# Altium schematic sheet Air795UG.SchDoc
size 431 x 279 mm
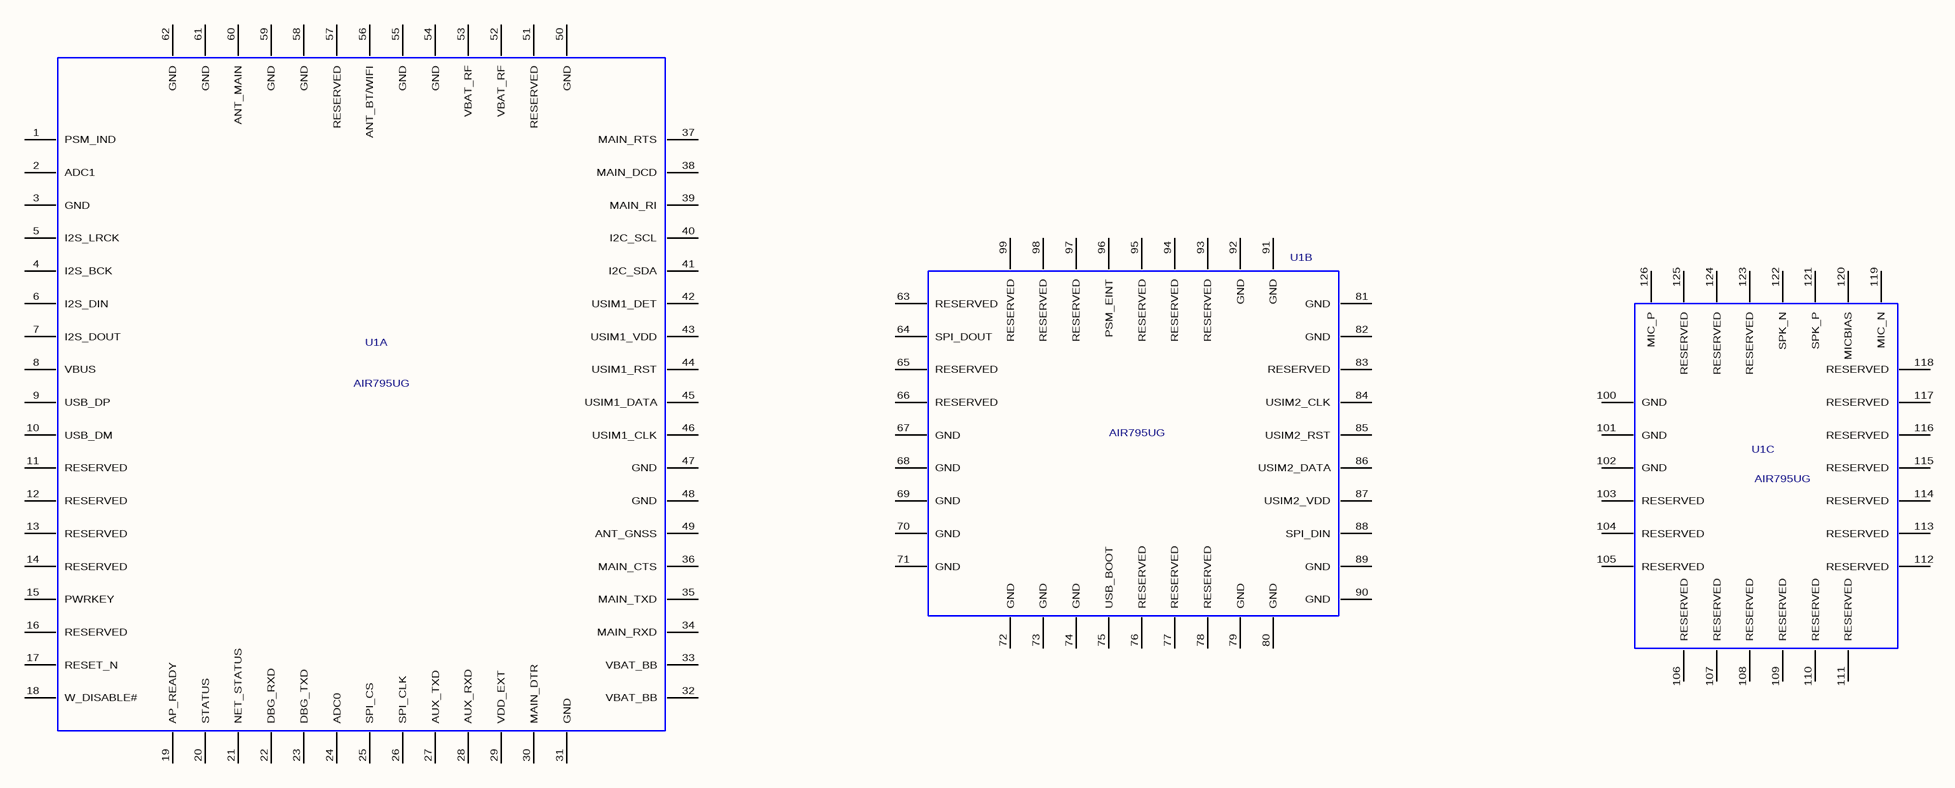
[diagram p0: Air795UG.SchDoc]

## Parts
U1  AIR795UG  [AIR795U-GL]  (parts A,B,C of 3)

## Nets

Not connected (* = marked no-connect by the designer): U1 1(PSM_IND) 2(ADC1) 3(GND) 4(I2S_BCK) 5(I2S_LRCK) 6(I2S_DIN) 7(I2S_DOUT) 8(VBUS) 9(USB_DP) 10(USB_DM) 11(RESERVED) 12(RESERVED) 13(RESERVED) 14(RESERVED) 15(PWRKEY) 16(RESERVED) 17(RESET_N) 18(W_DISABLE#) 19(AP_READY) 20(STATUS) 21(NET_STATUS) 22(DBG_RXD) 23(DBG_TXD) 24(ADC0) 25(SPI_CS) 26(SPI_CLK) 27(AUX_TXD) 28(AUX_RXD) 29(VDD_EXT) 30(MAIN_DTR) 31(GND) 32(VBAT_BB) 33(VBAT_BB) 34(MAIN_RXD) 35(MAIN_TXD) 36(MAIN_CTS) 37(MAIN_RTS) 38(MAIN_DCD) 39(MAIN_RI) 40(I2C_SCL) 41(I2C_SDA) 42(USIM1_DET) 43(USIM1_VDD) 44(USIM1_RST) 45(USIM1_DATA) 46(USIM1_CLK) 47(GND) 48(GND) 49(ANT_GNSS) 50(GND) 51(RESERVED) 52(VBAT_RF) 53(VBAT_RF) 54(GND) 55(GND) 56(ANT_BT/WIFI) 57(RESERVED) 58(GND) 59(GND) 60(ANT_MAIN) 61(GND) 62(GND) 63(RESERVED) 64(SPI_DOUT) 65(RESERVED) 66(RESERVED) 67(GND) 68(GND) 69(GND) 70(GND) 71(GND) 72(GND) 73(GND) 74(GND) 75(USB_BOOT) 76(RESERVED) 77(RESERVED) 78(RESERVED) 79(GND) 80(GND) 81(GND) 82(GND) 83(RESERVED) 84(USIM2_CLK) 85(USIM2_RST) 86(USIM2_DATA) 87(USIM2_VDD) 88(SPI_DIN) 89(GND) 90(GND) 91(GND) 92(GND) 93(RESERVED) 94(RESERVED) 95(RESERVED) 96(PSM_EINT) 97(RESERVED) 98(RESERVED) 99(RESERVED) 100(GND) 101(GND) 102(GND) 103(RESERVED) 104(RESERVED) 105(RESERVED) 106(RESERVED) 107(RESERVED) 108(RESERVED) 109(RESERVED) 110(RESERVED) 111(RESERVED) 112(RESERVED) 113(RESERVED) 114(RESERVED) 115(RESERVED) 116(RESERVED) 117(RESERVED) 118(RESERVED) 119(MIC_N) 120(MICBIAS) 121(SPK_P) 122(SPK_N) 123(RESERVED) 124(RESERVED) 125(RESERVED) 126(MIC_P)

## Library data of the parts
U1 = AIR795UG: Geometry.Height: 2.6 MM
